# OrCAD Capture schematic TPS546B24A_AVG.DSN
size Custom; title: TPS546B24A 2.95-V to 18-V, 20-A, up to 4× Stackable,; rev: 1.0; note: Datasheet: NA     EVM: NA; note: Synchronous Step Down Converter; note: PMBus® Buck Converter
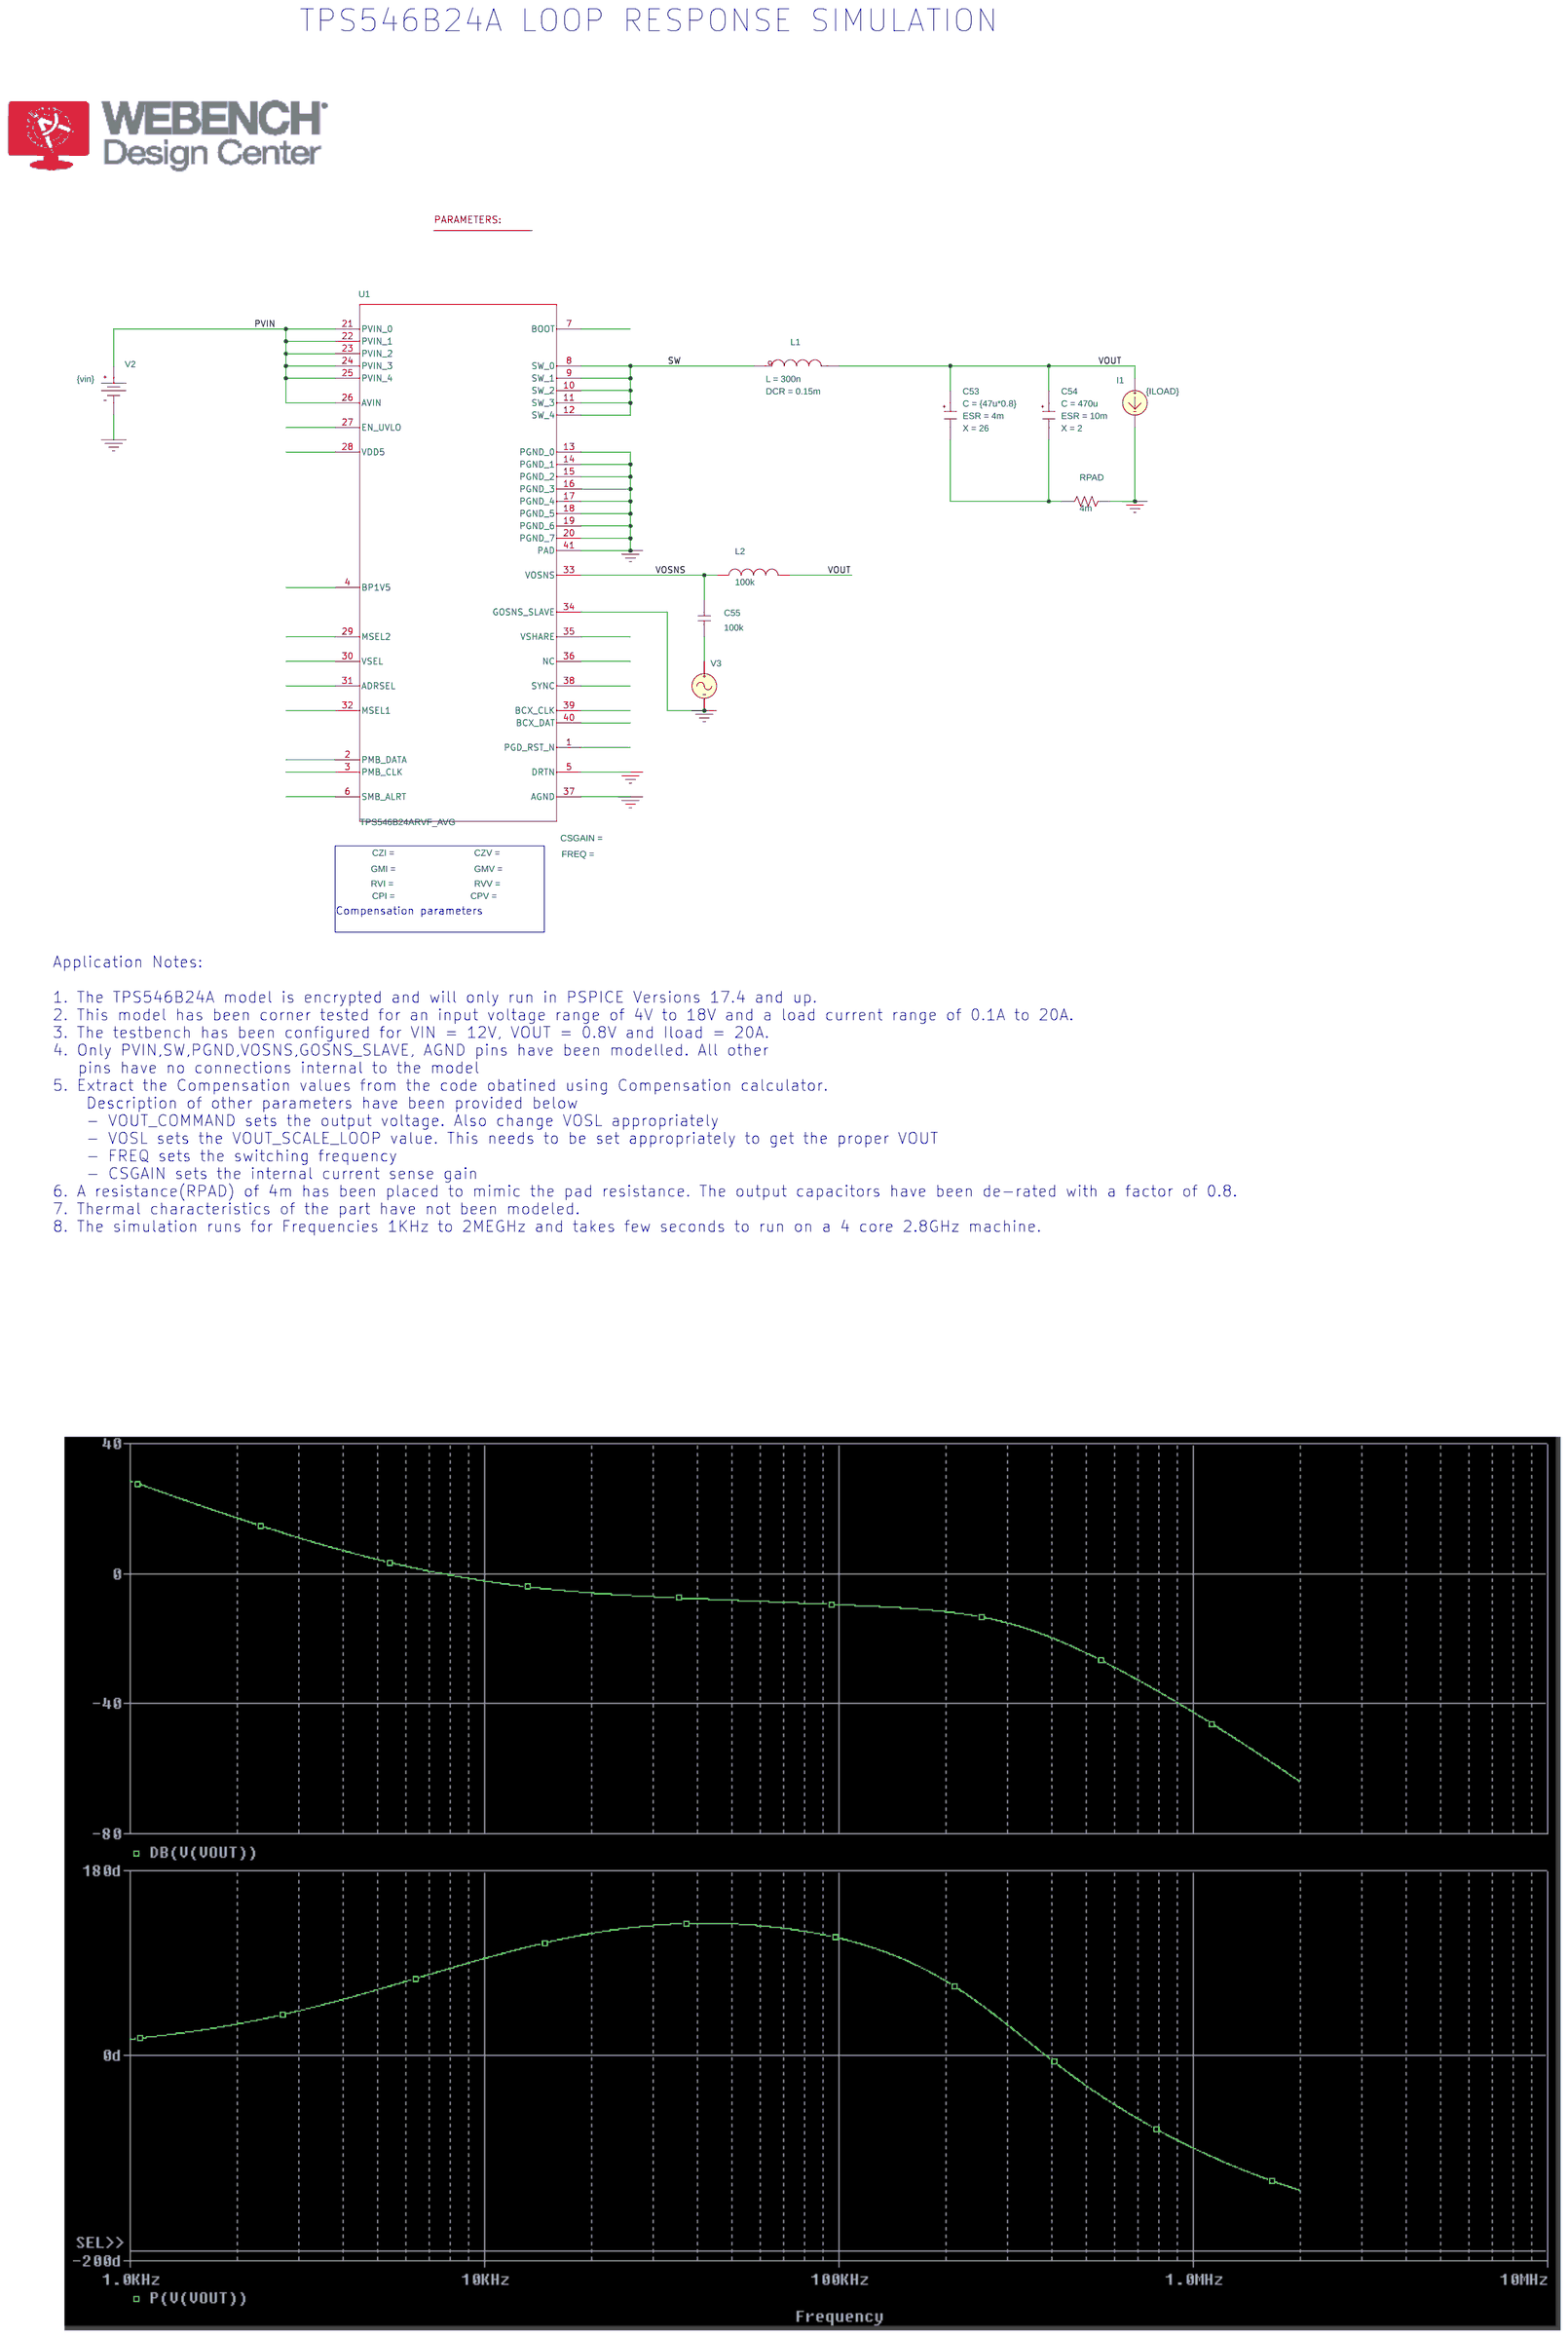
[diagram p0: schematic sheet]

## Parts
2  PARAM
C53  CESR
C54  CESR
C55  100k  [CK05]
I1  IDC
L1  LDCR
L2  100k  [L2012C]
RPAD  4m  [RC05]
U1  TPS546B24ARVF_AVG  [RVF0040A]
V2  VDC
V3  VAC

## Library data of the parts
2 = PARAM: ILOAD: 20; VIN: 12
C53 = CESR_2_1: C: {47u*0.8}; ESR: 4m; PSpiceTemplate: X^@REFDES %1 %2 @MODEL PARAMS:  ?C|C=@C||C=100u|  ?ESR|ESR=@ESR||ESR=0.01| ?X|X=@X||X=2|; X: 26
C54 = CESR_2: C: 470u; ESR: 10m; PSpiceTemplate: X^@REFDES %1 %2 @MODEL PARAMS:  ?C|C=@C||C=100u|  ?ESR|ESR=@ESR||ESR=0.01| ?X|X=@X||X=2|; X: 2
C55 = C
I1 = IDC: DC: {ILOAD}
L1 = LDCR_0: DCR: 0.15m; L: 300n; PSpiceTemplate: X^@REFDES %1 %2 @MODEL PARAMS:  ?L|L=@L||L=1u|  ?DCR|DCR=@DCR||DCR=0.01|
L2 = L
RPAD = R
U1 = TPS546B24ARVF_AVG
V2 = VDC: DC: {vin}
V3 = VAC

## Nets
PVIN: U1.21(PVIN_0) U1.22(PVIN_1) U1.23(PVIN_2) U1.24(PVIN_3) U1.25(PVIN_4) U1.26(AVIN) V2.0(+)
0: I1.2(-) RPAD.2 U1.5(DRTN) U1.13(PGND_0) U1.14(PGND_1) U1.15(PGND_2) U1.16(PGND_3) U1.17(PGND_4) U1.18(PGND_5) U1.19(PGND_6) U1.20(PGND_7) U1.34(GOSNS_SLAVE) U1.37(AGND) U1.41(PAD) V2.1(-) V3.2(-)
SW: L1.1 U1.8(SW_0) U1.9(SW_1) U1.10(SW_2) U1.11(SW_3) U1.12(SW_4)
VOSNS: C55.2 L2.1 U1.33(VOSNS)
VOUT: C53.1 C54.1 I1.1(+) L1.2 L2.2
N08661: C55.1 V3.1(+)
N08845: C53.2 C54.2 RPAD.1

Not connected (* = marked no-connect by the designer): U1 1(PGD_RST_N) 2(PMB_DATA) 3(PMB_CLK) 4(BP1V5) 6(SMB_ALRT) 7(BOOT) 27(EN_UVLO) 28(VDD5) 29(MSEL2) 30(VSEL) 31(ADRSEL) 32(MSEL1) 35(VSHARE) 36(NC) 38(SYNC) 39(BCX_CLK) 40(BCX_DAT)

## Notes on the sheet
- TPS546B24A LOOP RESPONSE SIMULATION
- Compensation parameters
- Application Notes:
  1. The TPS546B24A model is encrypted and will only run in PSPICE Versions 17.4 and up.
  2. This model has been corner tested for an input voltage range of 4V to 18V and a load current range of 0.1A to 20A.
  3. The testbench has been configured for VIN = 12V, VOUT = 0.8V and Iload = 20A.
  4. Only PVIN,SW,PGND,VOSNS,GOSNS_SLAVE, AGND pins have been modelled. All other
     pins have no connections internal to the model
  5. Extract the Compensation values from the code obatined using Compensation calculator.
      Description of other parameters have been provided below
      - VOUT_COMMAND sets the output voltage. Also change VOSL appropriately
      - VOSL sets the VOUT_SCALE_LOOP value. This needs to be set appropriately to get the proper VOUT
      - FREQ sets the switching frequency
      - CSGAIN sets the internal current sense gain
  6. A resistance(RPAD) of 4m has been placed to mimic the pad resistance. The output capacitors have been de-rated with a factor of 0.8.
  7. Thermal characteristics of the part have not been modeled.
  8. The simulation runs for Frequencies 1KHz to 2MEGHz and takes few seconds to run on a 4 core 2.8GHz machine.
